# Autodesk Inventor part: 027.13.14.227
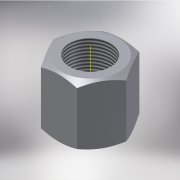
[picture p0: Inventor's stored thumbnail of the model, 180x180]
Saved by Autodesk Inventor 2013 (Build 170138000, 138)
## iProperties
Shininess: 64.0
Length Units: 11269
Angle Units: 11279
Time Units: 11290
Mass Units: 11283
Length Display Precision: 3
Angle Display Precision: 2
Created: 2002-02
Part Number: 027.13.14.227
Material: Steel, Mild
Document SubType Name: Modeling
Designer: SOleg
Density: 7.86 g/cm^3
Density: 0.0
Volumn: 0.0
Area: 0.0
PropertySet Name: Model Information
Control State: 0
Master: False
Checked Out: True
Checked Out Date: 2008-10-15
Last Check In Date: 2008-10-15
Author: SOleg
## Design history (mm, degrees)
sketch "Sketch1"
  geometry: L1 (11.836, 20.5)-(23.671, 0); L2 (23.671, 0)-(11.836, -20.5); L3 (11.836, -20.5)-(-11.836, -20.5); L4 (-11.836, -20.5)-(-23.671, 0); L5 (-23.671, 0)-(-11.836, 20.5); L6 (-11.836, 20.5)-(11.836, 20.5); C1 r 13.5 at (0, 0); 3 further points
  constraints: 12 end point, 2 coincident, 1 centre point, 1 midpoint, 1 vertical alignment, 13 other
  dimensions: "d1" = 27 diameter of C1
extrude "Extrusion1" new body sketch "Sketch1" distance "d2" = 40; taper "d3" = 0 deg
node "РабОсь1"
sketch "Sketch2"
  geometry: L1 (-19, 40)-(-32.041, 40); L2 (0, 45)-(0, -1.383); L3 (-19, 40)-(-32.041, 32.471); L4 (-32.041, 32.471)-(-32.041, 40); L5 (20.5, 0)-(20.5, 40) reference; L6 (20.5, 20)-(-24.004, 20); L7 (-19, 0)-(-32.041, 0); L8 (-19, 0)-(-32.041, 7.529); L9 (-32.041, 7.529)-(-32.041, 0); L10 (0, -10.66)-(0, 54.277) reference; L11 (13.5, 0)-(-13.5, 0) reference; L12 (20.5, 0)-(0, 0) reference; L13 (0, 0)-(-20.5, 0) reference; L14 (-20.5, 0)-(0, 0) reference; L15 (0, 0)-(20.5, 0) reference; L16 (-13.5, 40)-(13.5, 40) reference; L17 (20.5, 40)-(0, 40) reference; L18 (0, 40)-(20.5, 40) reference; L19 (-20.5, 40)-(0, 40) reference; L20 (0, 40)-(-20.5, 40) reference
  constraints: 16 end point, 3 collinear, 3 symmetric about line, 2 perpendicular, 1 midpoint, 3 other
  dimensions: "d5" = 30 deg angle of L1 L3; "d9" = 38 diameter of L7.start L2
revolve "Revolution1" sketch "Sketch2" stored, may be unused: angle "d6" = 90 deg
thread "Thread1" dims "d7" = 10, "d8" = 0
body "Solid1"
node "Спроецированная петля1"
node "Спроецированная петля2"
other parameters: "d0" = 41
